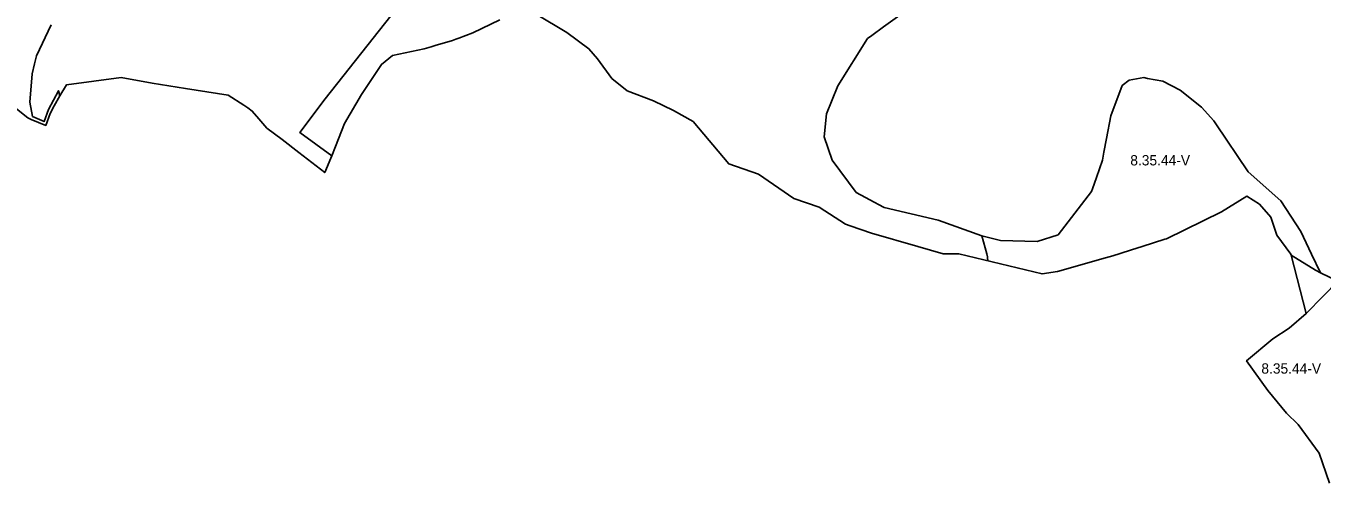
# Model space of a CAD drawing. Extents: x -547623 to -533936, y -1096714 to -1086523.
# Drawn here: x -545832 to -544574, y -1096124 to -1095680 of the extents above; entities that cross this region are included whole.
import ezdxf

# ---------------------------------------------------------------- set-up
doc = ezdxf.new("R2010")
doc.units = 0
doc.layers.add('Vrstva 27', color=7, linetype='Continuous')
doc.layers.add('Vrstva 28', color=7, linetype='Continuous')

msp = doc.modelspace()

# ---------------------------------------------------------------- linework, layer by layer
at = {"layer": 'Vrstva 28'}
for p, q in [((-544967, -1095657.5), (-545000, -1095681.3)), ((-545000, -1095681.3), (-544967, -1095657.5)), ((-545000, -1095681.3), (-545011.4, -1095689.6)), ((-545011.4, -1095689.6), (-545000, -1095681.3)), ((-545015.5, -1095692.5), (-545044.5, -1095738.5)), ((-545044.5, -1095738.5), (-545015.5, -1095692.5)), ((-545011.4, -1095689.6), (-545015.5, -1095692.5)), ((-545015.5, -1095692.5), (-545011.4, -1095689.6)), ((-544747.5, -1095730.5), (-544761.5, -1095733)), ((-544761.5, -1095733), (-544747.5, -1095730.5)), ((-544743.9, -1095731.2), (-544747.5, -1095730.5)), ((-544747.5, -1095730.5), (-544743.9, -1095731.2)), ((-544729, -1095734), (-544743.9, -1095731.2)), ((-544743.9, -1095731.2), (-544729, -1095734)), ((-545044.5, -1095738.5), (-545055.5, -1095765.5)), ((-545055.5, -1095765.5), (-545044.5, -1095738.5)), ((-544768.5, -1095738), (-544779.5, -1095767.5)), ((-544779.5, -1095767.5), (-544768.5, -1095738)), ((-544761.5, -1095733), (-544768.5, -1095738)), ((-544768.5, -1095738), (-544761.5, -1095733)), ((-544712, -1095742.5), (-544729, -1095734)), ((-544729, -1095734), (-544712, -1095742.5)), ((-544691.5, -1095759), (-544712, -1095742.5)), ((-544712, -1095742.5), (-544691.5, -1095759)), ((-545055.5, -1095765.5), (-545057.5, -1095788)), ((-545057.5, -1095788), (-545055.5, -1095765.5)), ((-544779.5, -1095767.5), (-544783.6, -1095789.7)), ((-544783.6, -1095789.7), (-544779.5, -1095767.5)), ((-544679.5, -1095772.5), (-544691.5, -1095759)), ((-544691.5, -1095759), (-544679.5, -1095772.5)), ((-544677.6, -1095775.4), (-544679.5, -1095772.5)), ((-544679.5, -1095772.5), (-544677.6, -1095775.4)), ((-544646, -1095822), (-544677.6, -1095775.4)), ((-544677.6, -1095775.4), (-544646, -1095822)), ((-545057.5, -1095788), (-545050, -1095810.5)), ((-545050, -1095810.5), (-545057.5, -1095788)), ((-544783.6, -1095789.7), (-544786.1, -1095802.9)), ((-544786.1, -1095802.9), (-544783.6, -1095789.7)), ((-544786.1, -1095802.9), (-544787.5, -1095810.5)), ((-544787.5, -1095810.5), (-544786.1, -1095802.9)), ((-545050, -1095810.5), (-545026.5, -1095842)), ((-545026.5, -1095842), (-545050, -1095810.5)), ((-544790.4, -1095818.9), (-544793.3, -1095827.5)), ((-544793.3, -1095827.5), (-544790.4, -1095818.9)), ((-544787.5, -1095810.5), (-544790.4, -1095818.9)), ((-544790.4, -1095818.9), (-544787.5, -1095810.5)), ((-544793.3, -1095827.5), (-544797.1, -1095838.4)), ((-544797.1, -1095838.4), (-544793.3, -1095827.5)), ((-544614.5, -1095850), (-544646, -1095822)), ((-544646, -1095822), (-544614.5, -1095850)), ((-545026.5, -1095842), (-545017.4, -1095846.9)), ((-545017.4, -1095846.9), (-545026.5, -1095842)), ((-544798, -1095841), (-544830.5, -1095883)), ((-544830.5, -1095883), (-544798, -1095841)), ((-544797.1, -1095838.4), (-544798, -1095841)), ((-544798, -1095841), (-544797.1, -1095838.4)), ((-545017.4, -1095846.9), (-545013.4, -1095849)), ((-545013.4, -1095849), (-545017.4, -1095846.9)), ((-545013.4, -1095849), (-545000, -1095856.2)), ((-545000, -1095856.2), (-545013.4, -1095849)), ((-545000, -1095856.2), (-544999.5, -1095856.5)), ((-544999.5, -1095856.5), (-545000, -1095856.2)), ((-544999.5, -1095856.5), (-544947, -1095869)), ((-544947, -1095869), (-544999.5, -1095856.5)), ((-544595, -1095880), (-544614.5, -1095850)), ((-544614.5, -1095850), (-544595, -1095880)), ((-544947, -1095869), (-544904.5, -1095884)), ((-544904.5, -1095884), (-544947, -1095869)), ((-544584.5, -1095901.8), (-544595, -1095880)), ((-544595, -1095880), (-544584.5, -1095901.8)), ((-544904.5, -1095884), (-544899.8, -1095901.4)), ((-544886.5, -1095888.5), (-544904.5, -1095884)), ((-544899.8, -1095901.4), (-544904.5, -1095884)), ((-544904.5, -1095884), (-544886.5, -1095888.5)), ((-544851, -1095889.5), (-544886.5, -1095888.5)), ((-544886.5, -1095888.5), (-544851, -1095889.5)), ((-544830.5, -1095883), (-544851, -1095889.5)), ((-544851, -1095889.5), (-544830.5, -1095883)), ((-544899.8, -1095901.4), (-544899.8, -1095901.4)), ((-544899.8, -1095901.4), (-544899, -1095904.5)), ((-544899, -1095904.5), (-544899.8, -1095901.4)), ((-544899.8, -1095901.4), (-544899.8, -1095901.4)), ((-544899, -1095904.5), (-544899, -1095905.3)), ((-544899, -1095905.3), (-544899, -1095904.5)), ((-544899, -1095905.3), (-544898.8, -1095908.4)), ((-544898.8, -1095908.4), (-544899, -1095905.3)), ((-544604.4, -1095902.7), (-544604.7, -1095901.8)), ((-544589.8, -1095959.6), (-544604.4, -1095902.7)), ((-544575.8, -1095919.9), (-544584.5, -1095901.8)), ((-544584.5, -1095901.8), (-544575.8, -1095919.9)), ((-544575.7, -1095920), (-544575.8, -1095919.9)), ((-544575.8, -1095919.9), (-544575.7, -1095920)), ((-544591, -1095960.7), (-544589.8, -1095959.6))]:
    msp.add_line(p, q, dxfattribs=at)
for points in [[(-545793, -1095737.5), (-545766.5, -1095733.9), (-545739.8, -1095730.5), (-545709.7, -1095735.8), (-545677.4, -1095741), (-545656.9, -1095744.4), (-545636, -1095747.4), (-545620.8, -1095757.2), (-545617.1, -1095759.8), (-545612.7, -1095762.9), (-545606.2, -1095770.4), (-545598.5, -1095779.5), (-545583.7, -1095790.7), (-545567.4, -1095803.2), (-545542.4, -1095822.7), (-545536.5, -1095808.6), (-545535.6, -1095806.4), (-545566.4, -1095783.8), (-545541.8, -1095751), (-545472.2, -1095662.6)], [(-545346, -1095663.8), (-545313.8, -1095682.8), (-545307.3, -1095686.6), (-545286, -1095702.5), (-545277.5, -1095712.1), (-545263.6, -1095731.2), (-545248.7, -1095743.2), (-545223.2, -1095753), (-545203.9, -1095762.5), (-545184.6, -1095773.1), (-545150.3, -1095814.3), (-545121.3, -1095824.1), (-545087, -1095847.9), (-545062.5, -1095856.1), (-545037, -1095872.7), (-545032.3, -1095874.3), (-545011.8, -1095881.4), (-544966.8, -1095894.4), (-544942.1, -1095901.6), (-544927, -1095901.6), (-544846.1, -1095921.1), (-544831.2, -1095918.7), (-544784.5, -1095905.4), (-544777.6, -1095903.4), (-544770.3, -1095901.1), (-544759.2, -1095897.6), (-544748.9, -1095894.3), (-544727.1, -1095887.4), (-544725.5, -1095886.9), (-544671.9, -1095860.8), (-544647.4, -1095845.7), (-544635.2, -1095853.4), (-544624, -1095865.8), (-544618.2, -1095883.4), (-544604.7, -1095901.8), (-544604.4, -1095902.7), (-544589.8, -1095959.6), (-544606.2, -1095973.6), (-544622.2, -1095984), (-544647.6, -1096005.3), (-544626.9, -1096034.1), (-544609, -1096056.1), (-544597.6, -1096067.2), (-544577.3, -1096095), (-544567.3, -1096124.1)], [(-545841.6, -1095760.7), (-545830.6, -1095769.5), (-545827.4, -1095771.2), (-545813.2, -1095776.9), (-545808.9, -1095765.3), (-545805.1, -1095757.8), (-545799.4, -1095748.3), (-545793, -1095737.5), (-545766.5, -1095733.9), (-545739.8, -1095730.5), (-545709.7, -1095735.8), (-545677.4, -1095741), (-545656.9, -1095744.4), (-545636, -1095747.4), (-545620.8, -1095757.2), (-545617.1, -1095759.8), (-545612.7, -1095762.9), (-545606.2, -1095770.4), (-545598.5, -1095779.5), (-545583.7, -1095790.7), (-545567.4, -1095803.2), (-545542.4, -1095822.7), (-545536.5, -1095808.6), (-545535.6, -1095806.4), (-545531.8, -1095797.3), (-545523.3, -1095775.1), (-545506.6, -1095746.8), (-545487.2, -1095717.6), (-545476.6, -1095709.1), (-545445.7, -1095702.5), (-545438.9, -1095700.5), (-545435.3, -1095699.4), (-545418.2, -1095694.4), (-545415.2, -1095693.3), (-545412.2, -1095692.1), (-545398.5, -1095686.9), (-545372.5, -1095674.4)], [(-545808, -1095679.3), (-545822, -1095709.3), (-545823.9, -1095717)], [(-545823.9, -1095717), (-545826.2, -1095726.9), (-545828.7, -1095754.2)], [(-545828.7, -1095754.2), (-545825.9, -1095768.2), (-545814.8, -1095773.1), (-545810.4, -1095761.3), (-545800.9, -1095743.2), (-545799.4, -1095748.3), (-545793, -1095737.5)], [(-544573.4, -1095942.7), (-544559.2, -1095927.9), (-544575.8, -1095919.9), (-544575.7, -1095920), (-544575.8, -1095919.9), (-544580.8, -1095917.5), (-544604.4, -1095902.7), (-544589.8, -1095959.6), (-544573.4, -1095942.7)]]:
    msp.add_lwpolyline(points, dxfattribs=at)

# ---------------------------------------------------------------- texts
at = {"layer": 'Vrstva 27'}
for p in [(-544760.5, -1095815.7), (-544633.3, -1096017.8)]:
    msp.add_text('8.35.44-V', height=10, dxfattribs=at).set_placement(p)

doc.saveas('drawing.dxf')
